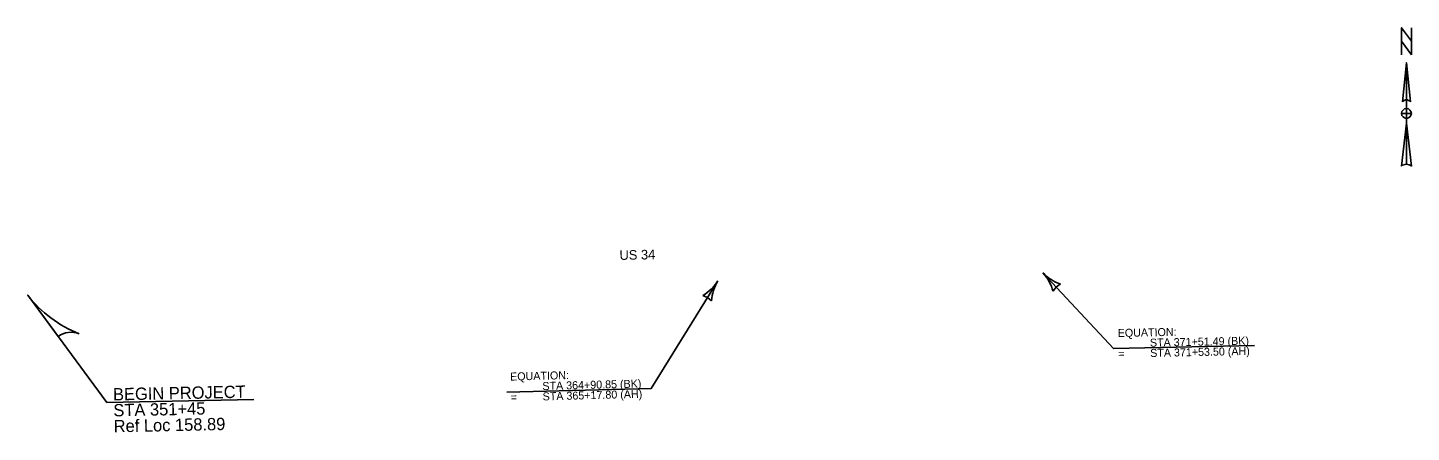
# Model space of a CAD drawing. Extents: x 22712865 to 22760106, y 6235088 to 6238602.
# Drawn here: x 22712865 to 22715562, y 6235323 to 6236112 of the extents above; entities that cross this region are included whole.
import ezdxf

# ---------------------------------------------------------------- set-up
doc = ezdxf.new("R2010")
doc.units = 0
for name, color, linetype in [('Contours Major', 7, 'Continuous'), ('Default', 7, 'Continuous'), ('Draft_3', 7, 'Continuous'), ('dsnTextOdd', 7, 'Continuous'), ('EdgeShoulder', 7, 'Continuous')]:
    doc.layers.add(name, color=color, linetype=linetype)

msp = doc.modelspace()

# ---------------------------------------------------------------- linework, layer by layer
at = {"layer": 'Contours Major'}
for points in [[(22714843.8, 6235633.8), (22714981.3, 6235485.8), (22715256.6, 6235491.8)], [(22714210.3, 6235618), (22714080.5, 6235408.2), (22713799.1, 6235400.7)]]:
    msp.add_lwpolyline(points, dxfattribs=at)
for centre, radius, start, end in [((22714781.5, 6235575.9), 85, 14.8149, 42.8874), ((22714906.1, 6235691.6), 85, 222.8874, 250.9599), ((22714138, 6235662.8), 85, 300.1768, 328.2493), ((22714282.6, 6235573.3), 85, 148.2493, 176.3218), ((22714892.3, 6235581.5), 32.8, 115.1541, 150.6208), ((22714172.8, 6235557.4), 32.8, 40.5159, 75.9826)]:
    msp.add_arc(centre, radius, start, end, dxfattribs=at)
at = {"layer": 'Draft_3'}
for p, q in [((22712924.2, 6235509.4), (22712864.8, 6235589.9)), ((22712865.6, 6235588.8), (22712865.3, 6235589.2)), ((22712924.2, 6235509.4), (22712924.2, 6235509.4))]:
    msp.add_line(p, q, dxfattribs=at)
msp.add_lwpolyline([(22712864.8, 6235589.9), (22713019.2, 6235380.8), (22713305.9, 6235386.8)], dxfattribs=at)
for centre, radius, start, end in [((22713055.1, 6235739.3), 242, 218.1307, 248.1607), ((22712949.3, 6235475.4), 42.4, 68.1603, 126.4456)]:
    msp.add_arc(centre, radius, start, end, dxfattribs=at)
at = {"layer": 'dsnTextOdd'}
for p, q in [((22715552.7, 6236043.1), (22715560.3, 6235967)), ((22715552.7, 6236043.1), (22715552.7, 6235845.3)), ((22715545.1, 6235967), (22715545.1, 6235967)), ((22715545.4, 6235967.7), (22715546.8, 6235969.3)), ((22715543.2, 6235841.5), (22715552.7, 6235925.2)), ((22715552.7, 6235934.7), (22715552.7, 6235934.7))]:
    msp.add_line(p, q, dxfattribs=at)
msp.add_lwpolyline([(22715562.2, 6236058.3), (22715543.2, 6236084.9), (22715543.2, 6236111.5), (22715562.2, 6236084.9)], close=True, dxfattribs=at)
for points in [[(22715543.2, 6236058.3), (22715543.2, 6236111.5), (22715562.2, 6236084.9), (22715562.2, 6236111.5)], [(22715545.1, 6235967), (22715552.7, 6236043.1), (22715552.7, 6235970.8)], [(22715562.2, 6235944.2), (22715552.7, 6235944.2), (22715552.7, 6235953.7)], [(22715552.7, 6235934.7), (22715552.7, 6235944.2), (22715543.2, 6235944.2)], [(22715552.7, 6235845.3), (22715552.7, 6235925.2), (22715562.2, 6235841.5)]]:
    msp.add_lwpolyline(points, dxfattribs=at)
for centre, radius, start, end in [((22715552.7, 6235944.2), 9.51, 90, 180), ((22715552.7, 6235961.3), 9.51, 90.0204, 143.1257), ((22715552.7, 6235961.3), 9.5, 36.8481, 90.0218), ((22715552.7, 6235944.2), 9.51, 0, 90), ((22715552.7, 6235944.2), 9.51, 180, 270), ((22715552.7, 6235944.2), 9.51, 270, 360), ((22715552.7, 6235831.5), 13.8, 89.9894, 133.619), ((22715552.7, 6235831.5), 13.8, 46.4021, 90.0006)]:
    msp.add_arc(centre, radius, start, end, dxfattribs=at)
at = {"layer": 'EdgeShoulder'}
msp.add_circle((22712864.7, 6235589.9), 0.05, dxfattribs=at)

# ---------------------------------------------------------------- texts
at = {"layer": 'Contours Major'}
for s, height, rotation, p in [('EQUATION:', 15.6, 1.1986, (22714989.9, 6235508.4)), ('STA 371+51.49 (BK)', 15.601, 1.1986, (22715052.7, 6235489.5)), ('STA 371+53.50 (AH)', 15.601, 1.1986, (22715053.2, 6235469.4)), ('=', 15.6, 1.1986, (22714990.8, 6235468.1)), ('EQUATION:', 15.6, 1.5081, (22713805.4, 6235423.4)), ('STA 364+90.85 (BK)', 15.601, 1.5081, (22713868.3, 6235404.9)), ('=', 15.6, 1.5081, (22713806.4, 6235383)), ('STA 365+17.80 (AH)', 15.601, 1.5081, (22713868.8, 6235384.7))]:
    msp.add_text(s, height=height, rotation=rotation, dxfattribs=at).set_placement(p)
at = {"layer": 'Default'}
msp.add_text('US 34', height=18.75, rotation=1.1652, dxfattribs=at).set_placement((22714018.7, 6235658.6))
at = {"layer": 'Draft_3'}
for s, height, p in [('BEGIN PROJECT', 24.001, (22713031.3, 6235384.6)), ('STA 351+45', 24, (22713032, 6235353.5)), ('Ref Loc 158.89', 24.001, (22713032.6, 6235322.5))]:
    msp.add_text(s, height=height, rotation=1.1986, dxfattribs=at).set_placement(p)

doc.saveas('drawing.dxf')
